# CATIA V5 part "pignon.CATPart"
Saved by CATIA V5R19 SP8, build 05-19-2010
Part number: pignon
Bounding box of the stored display mesh (mm): x 2.851 to 43.851, y 275.384 to 325.788, z 65.318 to 91.585
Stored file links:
  G:\EU_thinkMotion\CFAO_2010\MMS_groupe3\MMS_groupe3\A reprendre\amenand\amenand\pignon.CATPart
  F:\thinkmotion CFAO v12.1\essuie_glace.CATProduct
  G:\EU_thinkMotion\CFAO_2010\MMS_groupe3\MMS_groupe3\A reprendre\amenand\amenand\couronne.CATPart
  CATDrawing2.CATDrawing
  G:\EU_thinkMotion\CFAO_2010\MMS_groupe3\MMS_groupe3\A reprendre\amenand\amenand\squelette_pignon.CATPart
  G:\EU_thinkMotion\CFAO_2010\MMS_groupe3\MMS_groupe3\A reprendre\amenand\amenand\squelette_biellette3.CATPart
  G:\EU_thinkMotion\CFAO_2010\MMS_groupe3\MMS_groupe3\A reprendre\amenand\amenand\coulisseau.CATPart
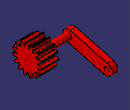
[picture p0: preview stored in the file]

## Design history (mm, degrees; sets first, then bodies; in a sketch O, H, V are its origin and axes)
Set1
  Plane1: linked copy from another document
  Plane2: linked copy from another document
  Line1: linked copy from another document
  Point1: linked copy from another document
  DatumCurve1: linked copy from another document
Body1 (main body)
  Sketch1 on Plane1, origin (43.8512, 251.964, 88.354), H (0, 1, 0), V (0, 0, 1)
    point P1 (36.1142, -9.5282)
    line L1 (44.8645, -12.9129) -> (45.9813, -13.3449)
    arc A1 centre (43.5733, -17.2219) radius 4.564 from (47.6031, -15.0793) to (45.9813, -13.3449) ccw
    line L2 (47.6031, -15.0793) -> (47.3804, -15.5185)
    line L3 (47.1409, -15.9487) -> (47.3804, -15.5185)
    arc A2 centre (46.6637, -11.4097) radius 4.564 from (44.7961, -15.5741) to (47.1409, -15.9487) ccw
    line L4 (43.8134, -14.8898) -> (44.7961, -15.5741)
    arc A3 centre (36.1142, -9.5282) radius 9.3821 from (42.7313, -16.1793) to (43.8134, -14.8898) ccw
    line L5 (42.7313, -16.1793) -> (43.5759, -17.0282)
    arc A4 centre (39.7991, -19.5906) radius 4.564 from (44.352, -19.2723) to (43.5759, -17.0282) ccw
    line L6 (44.352, -19.2723) -> (43.9699, -19.5829)
    line L7 (43.5761, -19.8785) -> (43.9699, -19.5829)
    arc A5 centre (44.9863, -15.5379) radius 4.564 from (41.5864, -18.5826) to (43.5761, -19.8785) ccw
    line L8 (40.967, -17.5578) -> (41.5864, -18.5826)
    arc A6 centre (36.1142, -9.5282) radius 9.3821 from (39.454, -18.2957) to (40.967, -17.5578) ccw
    line L9 (39.454, -18.2957) -> (39.8802, -19.4147)
    arc A7 centre (35.3878, -20.2194) radius 4.564 from (39.6765, -21.7805) to (39.8802, -19.4147) ccw
    line L10 (39.6765, -21.7805) -> (39.2011, -21.9088)
    line L11 (38.7211, -22.0187) -> (39.2011, -21.9088)
    arc A8 centre (41.7749, -18.627) radius 4.564 from (37.4305, -20.0255) to (38.7211, -22.0187) ccw
    line L12 (37.2815, -18.8374) -> (37.4305, -20.0255)
    arc A9 centre (36.1142, -9.5282) radius 9.3821 from (35.5991, -18.8961) to (37.2815, -18.8374) ccw
    line L13 (35.5991, -18.8961) -> (35.5334, -20.0918)
    arc A10 centre (31.102, -18.9997) radius 4.564 from (34.385, -22.1701) to (35.5334, -20.0918) ccw
    line L14 (34.385, -22.1701) -> (33.8985, -22.094)
    line L15 (33.4154, -21.9992) -> (33.8985, -22.094)
    arc A11 centre (37.5847, -20.1427) radius 4.564 from (33.0471, -19.6534) to (33.4154, -21.9991) ccw
    line L16 (33.3942, -18.5073) -> (33.0471, -19.6534)
    arc A12 centre (36.1142, -9.5282) radius 9.3821 from (31.8334, -17.8767) to (33.3942, -18.5073) ccw
    line L17 (31.8334, -17.8767) -> (31.287, -18.9423)
    arc A13 centre (27.683, -16.1422) radius 4.564 from (29.3925, -20.3738) to (31.287, -18.9423) ccw
    line L18 (29.3925, -20.3738) -> (28.9791, -20.1064)
    line L19 (28.5763, -19.8232) -> (28.9791, -20.1064)
    arc A14 centre (33.1402, -19.8231) radius 4.564 from (29.1939, -17.5305) to (28.5763, -19.8232) ccw
    line L20 (29.9772, -16.6247) -> (29.1939, -17.5305)
    arc A15 centre (36.1142, -9.5282) radius 9.3821 from (28.8078, -15.4138) to (29.9772, -16.6247) ccw
    line L21 (28.8078, -15.4138) -> (27.8753, -16.165)
    arc A16 centre (25.7217, -12.141) radius 4.564 from (25.5623, -16.7022) to (27.8753, -16.165) ccw
    line L22 (25.5623, -16.7022) -> (25.2934, -16.2898)
    line L23 (25.0406, -15.8672) -> (25.2934, -16.2898)
    arc A17 centre (29.21, -17.7235) radius 4.564 from (26.5374, -14.0239) to (25.0406, -15.8672) ccw
    line L24 (27.6213, -13.515) -> (26.5374, -14.0239)
    arc A18 centre (36.1142, -9.5282) radius 9.3821 from (27.0456, -11.9331) to (27.6213, -13.515) ccw
    line L25 (27.0456, -11.9331) -> (25.8881, -12.2401)
    arc A19 centre (25.5574, -7.6881) radius 4.564 from (23.5566, -11.7901) to (25.8881, -12.2401) ccw
    line L26 (23.5566, -11.7901) -> (23.4787, -11.304)
    line L27 (23.4196, -10.8151) -> (23.4787, -11.304)
    arc A20 centre (26.4736, -14.2067) radius 4.564 from (25.5368, -9.74) to (23.4196, -10.8151) ccw
    line L28 (26.734, -9.716) -> (25.5368, -9.74)
    arc A21 centre (36.1142, -9.5282) radius 9.3821 from (26.8514, -8.0367) to (26.734, -9.716) ccw
    line L29 (26.8514, -8.0367) -> (25.6692, -7.8463)
    arc A22 centre (27.2185, -3.5534) radius 4.564 from (23.7223, -6.487) to (25.6692, -7.8463) ccw
    line L30 (23.7223, -6.487) -> (23.8488, -6.0111)
    line L31 (23.9937, -5.5405) -> (23.8488, -6.0111)
    arc A23 centre (25.4041, -9.881) radius 4.564 from (26.3651, -5.4194) to (23.9937, -5.5405) ccw
    line L32 (27.4686, -5.8845) -> (26.3651, -5.4194)
    arc A24 centre (36.1142, -9.5282) radius 9.3821 from (28.2589, -4.3981) to (27.4686, -5.8845) ccw
    line L33 (28.2589, -4.3981) -> (27.2563, -3.7433)
    arc A25 centre (30.4178, -0.4517) radius 4.564 from (26.0306, -1.7096) to (27.2563, -3.7433) ccw
    line L34 (26.0306, -1.7096) -> (26.3397, -1.3264)
    line L35 (26.6635, -0.9554) -> (26.3397, -1.3264)
    arc A26 centre (26.1865, -5.4943) radius 4.564 from (28.8791, -1.8093) to (26.6635, -0.9554) ccw
    line L36 (29.698, -2.683) -> (28.8791, -1.8093)
    arc A27 centre (36.1142, -9.5282) radius 9.3821 from (31.0246, -1.6465) to (29.698, -2.683) ccw
    line L37 (31.0246, -1.6465) -> (30.375, -0.6406)
    arc A28 centre (34.602, 1.0805) radius 4.564 from (30.0824, 1.7158) to (30.375, -0.6406) ccw
    line L38 (30.0824, 1.7158) -> (30.5207, 1.9402)
    line L39 (30.9674, 2.1475) -> (30.5207, 1.9402)
    arc A29 centre (28.6855, -1.8051) radius 4.564 from (32.6442, 0.4662) to (30.9674, 2.1475) ccw
    line L40 (33.0369, -0.6651) -> (32.6442, 0.4662)
    arc A30 centre (36.1142, -9.5282) radius 9.3821 from (34.6703, -0.2578) to (33.0369, -0.6651) ccw
    line L41 (34.6703, -0.2578) -> (34.4861, 0.9254)
    arc A31 centre (39.0476, 0.7785) radius 4.564 from (35.1773, 3.1971) to (34.4861, 0.9254) ccw
    line L42 (35.1773, 3.1971) -> (35.6689, 3.2238)
    line L43 (36.1613, 3.2315) -> (35.6689, 3.2238)
    arc A32 centre (32.469, 0.5487) radius 4.564 from (37.0092, 1.0135) to (36.1613, 3.2315) ccw
    line L44 (36.9079, -0.1797) -> (37.0092, 1.0135)
    arc A33 centre (36.1142, -9.5282) radius 9.3821 from (38.5658, -0.472) to (36.9079, -0.1797) ccw
    arc A34 centre (42.9861, -1.3057) radius 4.564 from (40.4341, 2.478) to (38.8787, 0.6839) ccw
    line L45 (40.4341, 2.478) -> (40.8941, 2.3024)
    line L46 (41.347, 2.1092) -> (40.8941, 2.3024)
    arc A35 centre (36.8828, 1.1602) radius 4.564 from (41.2195, -0.2619) to (41.347, 2.1092) ccw
    line L47 (40.6417, -1.3107) -> (41.2195, -0.2619)
    arc A36 centre (36.1142, -9.5282) radius 9.3821 from (42.0373, -2.2521) to (40.6417, -1.3107) ccw
    line L48 (42.0373, -2.2521) -> (42.7933, -1.3234)
    arc A37 centre (45.7364, -4.8116) radius 4.564 from (44.944, -0.317) to (42.7933, -1.3234) ccw
    line L49 (44.944, -0.317) -> (45.2928, -0.6645)
    line L50 (45.6279, -1.0253) -> (45.2928, -0.6645)
    arc A38 centre (41.1637, -0.0765) radius 4.564 from (44.5471, -3.1395) to (45.6279, -1.0253) ccw
    line L51 (43.5926, -3.8626) -> (44.5471, -3.1395)
    arc A39 centre (36.1142, -9.5282) radius 9.3821 from (44.4847, -5.2902) to (43.5926, -3.8626) ccw
    line L52 (44.4847, -5.2902) -> (45.553, -4.7493)
    arc A40 centre (46.8229, -9.1331) radius 4.564 from (47.9271, -4.7047) to (45.553, -4.7493) ccw
    line L53 (47.9271, -4.7047) -> (48.1044, -5.1641)
    line L54 (48.2639, -5.6299) -> (48.1044, -5.1641)
    arc A41 centre (44.5715, -2.9474) radius 4.564 from (46.4165, -7.1218) to (48.2639, -5.6299) ccw
    line L55 (45.2504, -7.3942) -> (46.4165, -7.1218)
    arc A42 centre (36.1142, -9.5282) radius 9.3821 from (45.4847, -9.0612) to (45.2504, -7.3942) ccw
    line L56 (45.4847, -9.0612) -> (46.6807, -9.0016)
    arc A43 centre (46.0578, -13.5228) radius 4.564 from (48.8677, -9.9265) to (46.6807, -9.0016) ccw
    line L57 (48.8677, -9.9265) -> (48.8428, -10.4182)
    line L58 (48.799, -10.9087) -> (48.8428, -10.4182)
    arc A44 centre (46.5169, -6.9562) radius 4.564 from (46.5046, -11.5202) to (48.799, -10.9087) ccw
    line L59 (45.3285, -11.2947) -> (46.5046, -11.5202)
    arc A45 centre (36.1142, -9.5282) radius 9.3821 from (44.8645, -12.9129) to (45.3285, -11.2947) ccw
    circle A46 centre (36.1142, -9.5282) radius 3
    line L60 (38.5658, -0.472) -> (38.8787, 0.6839)
    point P4 (47.6031, -15.0793)
    point P6 (47.6031, -15.0793)
    point P7 (47.3804, -15.5185)
    point P9 (47.3804, -15.5185)
    point P10 (44.7961, -15.5741)
    point P13 (44.7961, -15.5741)
    point P18 (44.352, -19.2723)
    point P20 (44.352, -19.2723)
    point P21 (43.9699, -19.5829)
    point P23 (43.9699, -19.5829)
    point P24 (41.5864, -18.5826)
    point P27 (41.5864, -18.5826)
    point P32 (39.6765, -21.7805)
    point P34 (39.6765, -21.7805)
    point P35 (39.2011, -21.9088)
    point P37 (39.2011, -21.9088)
    point P38 (37.4305, -20.0255)
    point P41 (37.4305, -20.0255)
    point P46 (34.385, -22.1701)
    point P48 (34.385, -22.1701)
    point P49 (33.8985, -22.094)
    point P51 (33.8985, -22.094)
    point P52 (33.0471, -19.6534)
    point P55 (33.0471, -19.6534)
    point P60 (29.3925, -20.3738)
    point P62 (29.3925, -20.3738)
    point P63 (28.9791, -20.1064)
    point P65 (28.9791, -20.1064)
    point P66 (29.1939, -17.5305)
    point P69 (29.1939, -17.5305)
    point P74 (25.5623, -16.7022)
    point P76 (25.5623, -16.7022)
    point P77 (25.2934, -16.2898)
    point P79 (25.2934, -16.2898)
    point P80 (26.5374, -14.0239)
    point P83 (26.5374, -14.0239)
    point P88 (23.5566, -11.7901)
    point P90 (23.5566, -11.7901)
    point P91 (23.4787, -11.304)
    point P92 (23.4196, -10.8151)
    point P93 (23.4787, -11.304)
    point P94 (25.5368, -9.74)
    point P95 (23.4196, -10.8151)
    point P97 (25.5368, -9.74)
    point P102 (23.7223, -6.487)
    point P104 (23.7223, -6.487)
    point P105 (23.8488, -6.0111)
    point P107 (23.8488, -6.0111)
    point P108 (26.3651, -5.4194)
    point P110 (27.4686, -5.8845)
    point P111 (26.3651, -5.4194)
    point P112 (28.2589, -4.3981)
    point P113 (27.4686, -5.8845)
    point P114 (28.2589, -4.3981)
    point P116 (26.0306, -1.7096)
    point P118 (26.0306, -1.7096)
    point P119 (26.3397, -1.3264)
    point P121 (26.3397, -1.3264)
    point P122 (28.8791, -1.8093)
    point P124 (29.698, -2.683)
    point P125 (28.8791, -1.8093)
    point P126 (31.0246, -1.6465)
    point P127 (29.698, -2.683)
    point P128 (31.0246, -1.6465)
    point P130 (30.0824, 1.7158)
    point P132 (30.0824, 1.7158)
    point P133 (30.5207, 1.9402)
    point P135 (30.5207, 1.9402)
    point P136 (32.6442, 0.4662)
    point P139 (32.6442, 0.4662)
    point P144 (35.1773, 3.1971)
    point P146 (35.1773, 3.1971)
    point P147 (35.6689, 3.2238)
    point P149 (35.6689, 3.2238)
    point P150 (37.0092, 1.0135)
    point P153 (37.0092, 1.0135)
    point P156 (40.4341, 2.478)
    point P158 (40.4341, 2.478)
    point P159 (40.8941, 2.3024)
    point P161 (40.8941, 2.3024)
    point P162 (41.2195, -0.2619)
    point P165 (41.2195, -0.2619)
    point P170 (44.944, -0.317)
    point P172 (44.944, -0.317)
    point P173 (45.2928, -0.6645)
    point P175 (45.2928, -0.6645)
    point P176 (44.5471, -3.1395)
    point P179 (44.5471, -3.1395)
    point P184 (47.9271, -4.7047)
    point P186 (47.9271, -4.7047)
    point P187 (48.1044, -5.1641)
    point P189 (48.1044, -5.1641)
    point P190 (46.4165, -7.1218)
    point P193 (46.4165, -7.1218)
    point P198 (48.8677, -9.9265)
    point P200 (48.8677, -9.9265)
    point P201 (48.8428, -10.4182)
    point P203 (48.8428, -10.4182)
    point P204 (46.5046, -11.5202)
    point P207 (46.5046, -11.5202)
    radius A46 = 3
    coincidence: P4 P6, P7 P9, P10 P13, P18 P20, P21 P23, P24 P27, P32 P34, P35 P37, P38 P41, P46 P48, P49 P51, P52 P55, P60 P62, P63 P65, P66 P69, P74 P76, P77 P79, P80 P83, P88 P90, P91 P93, P94 P97, P102 P104, P105 P107, P108 P111, P112 P114, P116 P118, P119 P121, P122 P125, P126 P128, P130 P132, P133 P135, P136 P139, P144 P146, P147 P149, P150 P153, P156 P158, P159 P161, P162 P165, P170 P172, P173 P175, P176 P179, P184 P186, P187 P189, P190 P193, P198 P200, P201 P203, P204 P207, P92 P95, P110 P113, P124 P127
  Pad1: profile Sketch1, direction (-1, 0, 0), length 15
  Plane3: stored without definition
  Sketch2 on Plane1, origin (43.8512, 251.964, 88.354), H (0, 1, 0), V (0, 0, 1)
    circle A1 centre (36.1142, -9.5282) radius 3
    reference projected circle E1 centre (36.1142, -9.5282) radius 3 from edge [face of Pad1 from Sketch1.A46 | end face of Pad1]
    coincidence: A1 E1
  Pad2: profile Sketch2, direction (1, 0, 0), up to Plane3
  Plane4: stored without definition
  Sketch3 on Plane2, origin (7.8512, 309.2899, 86.4007), H (0, 1, 0), V (0, 0, 1)
    circle A1 centre (-21.2117, -7.5749) radius 3
    arc A2 centre (-21.2117, -7.5749) radius 5 from (-19.9362, -2.7403) to (-22.4872, -12.4094) ccw
    circle A3 centre (11.6633, -16.2484) radius 2
    arc A4 centre (11.6633, -16.2484) radius 5 from (10.3878, -21.083) to (12.9389, -11.4139) ccw
    point P4 (11.6633, -16.2484)
    reference projected circle E1 centre (-21.2117, -7.5749) radius 3 from edge [end face of Pad2 | face of Pad2 from Sketch2.A1]
    reference projected point E2 (11.6633, -16.2484) from Point1
    line L1 (12.9389, -11.4139) -> (-19.9362, -2.7403)
    point P6 (-19.9362, -2.7403)
    line L2 (10.3878, -21.083) -> (-22.4872, -12.4094)
    point P7 (10.3878, -21.083)
    reference projected line E3 (12.2918, -16.4142) -> (-57.3259, 1.9533) from Line1
    point P9 (-19.9362, -2.7403)
    point P10 (10.3878, -21.083)
    radius A2 = 5
    radius A3 = 2
    radius A4 = 5
    concentricity: A1 A2, A4 A3
    coincidence: A1 E1, P4 E2, P7 A4, P6 A2, L1 P9, L2 P10, P6 P9, P7 P10
    parallelism: L2 L1, L2 E3
    tangency: L2 A2, L1 A4
  Pad3: profile Sketch3, direction (1, 0, 0), up to Plane4
  Sketch4 on Plane1, origin (43.8512, 0, 0), H (0, 1, 0), V (0, 0, 1)
    circle A1 centre (288.0782, 78.8258) radius 11.25
    reference projected circle E1 centre (288.0782, 78.8258) radius 11.25 from edge of DatumCurve1
    coincidence: A1 E1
